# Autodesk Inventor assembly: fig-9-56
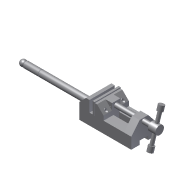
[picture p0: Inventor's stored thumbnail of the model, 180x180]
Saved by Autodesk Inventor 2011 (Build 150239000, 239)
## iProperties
Created: 2009-05
Part Number: fig-9-56
Document SubType Name: Assembly
Designer: Sham
Author: Sham
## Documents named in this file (9)
- C:\Users\CADSoft\Desktop\inventor\c09-inv-2010-prt\c09\Drill Press Vice\fig-9-56.iam
- C:\Users\CADSoft\Desktop\inventor\c09-inv-2010-prt\c09\Drill Press Vice\Base.ipt
- C:\Users\CADSoft\Desktop\inventor\c09-inv-2010-prt\c09\Drill Press Vice\Safety Handle.ipt
- C:\Users\CADSoft\Desktop\inventor\c09-inv-2010-prt\c09\Drill Press Vice\Jaw Face.ipt
- C:\Users\CADSoft\Desktop\inventor\c09-inv-2010-prt\c09\Drill Press Vice\Movable Jaw.ipt
- C:\Users\CADSoft\Desktop\inventor\c09-inv-2010-prt\c09\Drill Press Vice\Cap Screw.ipt
- C:\Users\CADSoft\Desktop\inventor\c09-inv-2010-prt\c09\Drill Press Vice\Clamp Screw Handle.ipt
- C:\Users\CADSoft\Desktop\inventor\c09-inv-2010-prt\c09\Drill Press Vice\Clamp Screw.ipt
- C:\Users\CADSoft\Desktop\inventor\c09-inv-2010-prt\c09\Drill Press Vice\Handle Stop.ipt
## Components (10 placed, 8 different names)
1. Base:1 — Mate:1, Mate:2, Mate:3, Flush:1
2. Safety Handle:1
3. Jaw Face:1 — Mate:1, Mate:4, Flush:1
4. Movable Jaw:1 — Mate:2, Mate:3, Mate:4, Insert:2, Insert:3, Insert:4
5. Cap Screw:1 — Insert:2
6. Cap Screw:2 — Insert:3
7. Clamp Screw:1 — Insert:4, Mate:6
8. Clamp Screw Handle:1 — Mate:6, Insert:5, Insert:6
9. Handle Stop:1 — Insert:6
10. Handle Stop:2 — Insert:5
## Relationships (11: Mate 5, Insert 5, Flush 1)
- Mate:1: Base:1 ↔ Jaw Face:1
- Mate:2: Base:1 ↔ Movable Jaw:1
- Mate:3: Base:1 ↔ Movable Jaw:1
- Mate:4: Jaw Face:1 ↔ Movable Jaw:1
- Insert:2: Movable Jaw:1 ↔ Cap Screw:1
- Insert:3: Movable Jaw:1 ↔ Cap Screw:2
- Insert:4: Movable Jaw:1 ↔ Clamp Screw:1
- Mate:6: Clamp Screw:1 ↔ Clamp Screw Handle:1
- Insert:5: Clamp Screw Handle:1 ↔ Handle Stop:2
- Insert:6: Clamp Screw Handle:1 ↔ Handle Stop:1
- Flush:1: Base:1 ↔ Jaw Face:1
